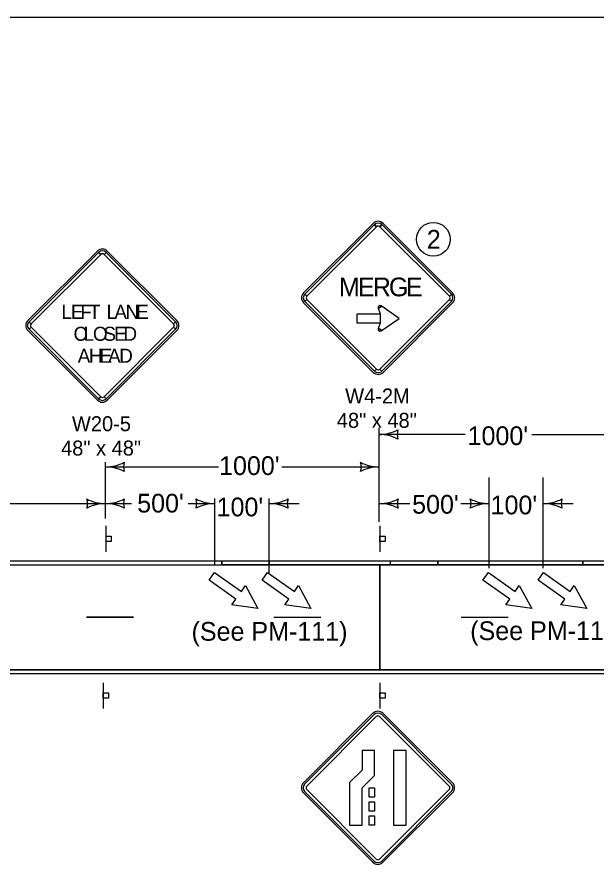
# Model space of a CAD drawing. Extents: x -2135039 to 114557, y -2139150 to -409929.
# Drawn here: x -2134068 to -2133449, y -2137945 to -2137036 of the extents above; entities that cross this region are included whole.
import ezdxf

# ---------------------------------------------------------------- set-up
doc = ezdxf.new("R2010")
doc.units = 0
for name, color, linetype in [('dsnStdLabel', 7, 'Continuous'), ('dsnStdLineWork', 7, 'Continuous'), ('dsnStdNote', 7, 'Continuous'), ('dsnStdShading', 7, 'Continuous'), ('Level 1', 7, 'Continuous'), ('StdDimension', 7, 'Continuous')]:
    doc.layers.add(name, color=color, linetype=linetype)

msp = doc.modelspace()

# ---------------------------------------------------------------- linework, layer by layer
at = {"layer": 'dsnStdLabel'}
for p, q in [((-2133688.07, -2137256.29), (-2133762.32, -2137330.54)), ((-2133686.75, -2137257.62), (-2133684.54, -2137259.83)), ((-2133681, -2137259.83), (-2133678.79, -2137257.62)), ((-2133603.22, -2137330.54), (-2133677.47, -2137256.29)), ((-2133982.39, -2137285.89), (-2134056.63, -2137360.14)), ((-2133897.53, -2137360.14), (-2133971.78, -2137285.89)), ((-2133981.06, -2137287.22), (-2133978.85, -2137289.43)), ((-2133975.32, -2137289.43), (-2133973.11, -2137287.22)), ((-2133758.79, -2137334.08), (-2133760.99, -2137331.87)), ((-2133760.99, -2137339.82), (-2133758.79, -2137337.61)), ((-2133604.55, -2137331.87), (-2133606.76, -2137334.08)), ((-2133606.76, -2137337.61), (-2133604.55, -2137339.82)), ((-2133762.32, -2137341.15), (-2133688.07, -2137415.39)), ((-2133682.67, -2137346.8), (-2133680.74, -2137346.16)), ((-2133680.74, -2137346.16), (-2133679.65, -2137344.44)), ((-2133677.47, -2137415.39), (-2133603.22, -2137341.15)), ((-2134053.1, -2137363.68), (-2134055.31, -2137361.47)), ((-2134055.31, -2137369.42), (-2134053.1, -2137367.21)), ((-2133898.86, -2137361.47), (-2133901.07, -2137363.68)), ((-2133901.07, -2137367.21), (-2133898.86, -2137369.42)), ((-2134056.63, -2137370.75), (-2133982.39, -2137444.99)), ((-2133971.78, -2137444.99), (-2133897.53, -2137370.75)), ((-2133680.74, -2137369.28), (-2133682.67, -2137368.63)), ((-2133679.65, -2137371), (-2133680.74, -2137369.28)), ((-2133684.54, -2137411.86), (-2133686.75, -2137414.07)), ((-2133678.79, -2137414.07), (-2133681, -2137411.86)), ((-2133978.85, -2137441.46), (-2133981.06, -2137443.67)), ((-2133973.11, -2137443.67), (-2133975.32, -2137441.46)), ((-2133973.24, -2137579.41), (-2133973.24, -2137606.91)), ((-2133680.95, -2137579.41), (-2133680.95, -2137606.91)), ((-2133976.34, -2137746.91), (-2133976.34, -2137774.41)), ((-2133680.95, -2137746.91), (-2133680.95, -2137774.41)), ((-2133688.27, -2137779.43), (-2133762.52, -2137853.68)), ((-2133762.52, -2137853.68), (-2133688.27, -2137779.44)), ((-2133761.19, -2137855.01), (-2133686.95, -2137780.76)), ((-2133684.74, -2137782.97), (-2133758.98, -2137857.22)), ((-2133688.27, -2137779.44), (-2133688.27, -2137779.43)), ((-2133684.74, -2137782.97), (-2133684.74, -2137782.97)), ((-2133606.95, -2137857.22), (-2133681.2, -2137782.97)), ((-2133678.99, -2137780.76), (-2133604.74, -2137855.01)), ((-2133603.42, -2137853.68), (-2133677.67, -2137779.43)), ((-2133677.67, -2137779.44), (-2133603.42, -2137853.68)), ((-2133688.27, -2137938.54), (-2133762.52, -2137864.29)), ((-2133762.52, -2137864.29), (-2133688.27, -2137938.54)), ((-2133686.95, -2137937.21), (-2133761.19, -2137862.96)), ((-2133758.98, -2137860.75), (-2133684.74, -2137935)), ((-2133681.2, -2137935), (-2133606.95, -2137860.75)), ((-2133604.74, -2137862.96), (-2133678.99, -2137937.21)), ((-2133603.42, -2137864.29), (-2133677.67, -2137938.54)), ((-2133677.67, -2137938.54), (-2133603.42, -2137864.29))]:
    msp.add_line(p, q, dxfattribs=at)
for points in [[(-2133686.75, -2137257.62), (-2133760.99, -2137331.87), (-2133758.79, -2137334.08), (-2133684.54, -2137259.83), (-2133686.75, -2137257.62)], [(-2133604.55, -2137331.87), (-2133678.79, -2137257.62), (-2133681, -2137259.83), (-2133606.76, -2137334.08), (-2133604.55, -2137331.87)], [(-2133981.06, -2137287.22), (-2134055.31, -2137361.47), (-2134053.1, -2137363.68), (-2133978.85, -2137289.43), (-2133981.06, -2137287.22)], [(-2133898.86, -2137361.47), (-2133973.11, -2137287.22), (-2133975.32, -2137289.43), (-2133901.07, -2137363.68), (-2133898.86, -2137361.47)], [(-2133760.99, -2137339.82), (-2133686.75, -2137414.07), (-2133684.54, -2137411.86), (-2133758.79, -2137337.61), (-2133760.99, -2137339.82)], [(-2133678.79, -2137414.07), (-2133604.55, -2137339.82), (-2133606.76, -2137337.61), (-2133681, -2137411.86), (-2133678.79, -2137414.07)], [(-2133660.43, -2137357.72), (-2133679.65, -2137344.44), (-2133680.74, -2137346.16), (-2133682.67, -2137346.8), (-2133680.68, -2137352.72), (-2133680.68, -2137362.72), (-2133682.67, -2137368.63), (-2133680.74, -2137369.28), (-2133679.65, -2137371), (-2133660.43, -2137357.72)], [(-2133705.11, -2137362.72), (-2133705.11, -2137352.72), (-2133680.68, -2137352.72), (-2133680.68, -2137362.72), (-2133705.11, -2137362.72)], [(-2134055.31, -2137369.42), (-2133981.06, -2137443.67), (-2133978.85, -2137441.46), (-2134053.1, -2137367.21), (-2134055.31, -2137369.42)], [(-2133973.11, -2137443.67), (-2133898.86, -2137369.42), (-2133901.07, -2137367.21), (-2133975.32, -2137441.46), (-2133973.11, -2137443.67)], [(-2133973.14, -2137595.86), (-2133973.14, -2137590.23), (-2133967.52, -2137590.23), (-2133967.52, -2137595.86)], [(-2133680.86, -2137595.86), (-2133680.86, -2137590.23), (-2133675.23, -2137590.23), (-2133675.23, -2137595.86)], [(-2133976.24, -2137763.35), (-2133976.24, -2137757.73), (-2133970.62, -2137757.73), (-2133970.62, -2137763.35)], [(-2133680.86, -2137763.35), (-2133680.86, -2137757.73), (-2133675.23, -2137757.73), (-2133675.23, -2137763.35)], [(-2133699.97, -2137840.14), (-2133713.22, -2137853.39), (-2133713.22, -2137898.99), (-2133699.72, -2137898.99), (-2133699.72, -2137858.99), (-2133686.47, -2137845.73), (-2133686.47, -2137818.99), (-2133699.97, -2137818.99)], [(-2133666.22, -2137818.99), (-2133666.22, -2137898.99), (-2133652.72, -2137898.99), (-2133652.72, -2137818.99)], [(-2133692.47, -2137858.99), (-2133686.47, -2137858.99), (-2133686.47, -2137868.99), (-2133692.47, -2137868.99)], [(-2133692.47, -2137873.99), (-2133686.47, -2137873.99), (-2133686.47, -2137883.99), (-2133692.47, -2137883.99)], [(-2133692.47, -2137888.99), (-2133686.47, -2137888.99), (-2133686.47, -2137898.99), (-2133692.47, -2137898.99)]]:
    msp.add_lwpolyline(points, close=True, dxfattribs=at)
for points in [[(-2133686.95, -2137780.76), (-2133761.19, -2137855.01)], [(-2133684.74, -2137782.97), (-2133758.99, -2137857.22)], [(-2133606.95, -2137857.22), (-2133681.2, -2137782.97)], [(-2133604.74, -2137855.01), (-2133678.99, -2137780.76)], [(-2133761.19, -2137862.96), (-2133686.95, -2137937.21)], [(-2133758.99, -2137860.75), (-2133684.74, -2137935)], [(-2133681.2, -2137935), (-2133606.95, -2137860.75)], [(-2133678.99, -2137937.21), (-2133604.74, -2137862.96)]]:
    msp.add_lwpolyline(points, dxfattribs=at)
for centre, radius, start, end in [((-2133682.77, -2137261.6), 7.5, 44.99999, 134.99974), ((-2133682.77, -2137261.6), 5.62, 44.99999, 134.99974), ((-2133682.77, -2137261.6), 2.5, 44.99999, 134.99974), ((-2133977.08, -2137291.2), 7.5, 44.99999, 134.99974), ((-2133977.08, -2137291.2), 5.62, 44.99999, 134.99974), ((-2133977.08, -2137291.2), 2.5, 44.99999, 134.99974), ((-2133757.02, -2137335.84), 7.5, 134.99974, 224.99995), ((-2133608.53, -2137335.84), 7.5, 315.00016, 44.9998), ((-2133757.02, -2137335.84), 5.62, 134.99974, 224.99995), ((-2133757.02, -2137335.84), 2.5, 134.99974, 224.99995), ((-2133608.53, -2137335.84), 2.5, 315.00016, 44.9998), ((-2133608.53, -2137335.84), 5.62, 315.00016, 44.9998), ((-2133680.74, -2137346.16), 2.03, 57.68768, 198.58144), ((-2134051.33, -2137365.44), 7.5, 134.99974, 224.99995), ((-2134051.33, -2137365.44), 5.62, 134.99974, 224.99995), ((-2134051.33, -2137365.44), 2.5, 134.99974, 224.99995), ((-2133902.84, -2137365.44), 2.5, 315.00016, 44.9998), ((-2133902.84, -2137365.44), 5.62, 315.00016, 44.9998), ((-2133902.84, -2137365.44), 7.5, 315.00016, 44.9998), ((-2133680.74, -2137369.28), 2.03, 161.41825, 302.31259), ((-2133682.77, -2137410.09), 2.5, 224.99995, 315.00016), ((-2133682.77, -2137410.09), 7.5, 224.99995, 315.00016), ((-2133682.77, -2137410.09), 5.62, 224.99995, 315.00016), ((-2133977.08, -2137439.69), 7.5, 224.99995, 315.00016), ((-2133977.08, -2137439.69), 5.62, 224.99995, 315.00016), ((-2133977.08, -2137439.69), 2.5, 224.99995, 315.00016), ((-2133682.97, -2137784.74), 7.5, 45.00026, 135.00001), ((-2133682.97, -2137784.74), 7.5, 45.00026, 135.00001), ((-2133682.97, -2137784.74), 5.63, 45.00026, 135.00001), ((-2133682.97, -2137784.74), 5.63, 45.00026, 135.00001), ((-2133682.97, -2137784.74), 2.5, 45.00026, 135.00001), ((-2133682.97, -2137784.74), 2.5, 45.00026, 135.00001), ((-2133757.22, -2137858.99), 7.5, 135.0002, 224.99984), ((-2133757.22, -2137858.99), 7.5, 135.0002, 224.99984), ((-2133757.22, -2137858.99), 5.63, 135.0002, 224.99984), ((-2133757.22, -2137858.99), 5.63, 135.0002, 224.99984), ((-2133757.22, -2137858.99), 2.5, 135.0002, 224.99984), ((-2133757.22, -2137858.99), 2.5, 135.0002, 224.99984), ((-2133608.72, -2137858.99), 2.5, 315.00005, 45.00026), ((-2133608.72, -2137858.99), 2.5, 315.00005, 45.00026), ((-2133608.72, -2137858.99), 5.63, 315.00005, 45.00026), ((-2133608.72, -2137858.99), 5.63, 315.00005, 45.00026), ((-2133608.72, -2137858.99), 7.5, 315.00005, 45.00026), ((-2133608.72, -2137858.99), 7.5, 315.00005, 45.00026), ((-2133682.97, -2137933.23), 7.5, 224.99984, 315.00005), ((-2133682.97, -2137933.23), 7.5, 224.99984, 315.00005), ((-2133682.97, -2137933.23), 5.63, 224.99984, 315.00005), ((-2133682.97, -2137933.23), 5.63, 224.99984, 315.00005), ((-2133682.97, -2137933.23), 2.5, 224.99984, 315.00005), ((-2133682.97, -2137933.23), 2.5, 224.99984, 315.00005)]:
    msp.add_arc(centre, radius, start, end, dxfattribs=at)
at = {"layer": 'dsnStdLineWork'}
for p, q in [((-2134890.21, -2137620.91), (-2133281.94, -2137620.91)), ((-2133863.14, -2137637.37), (-2133857.4, -2137629.18)), ((-2133857.4, -2137629.18), (-2133828.74, -2137649.25)), ((-2133806.58, -2137637.37), (-2133800.85, -2137629.18)), ((-2133800.85, -2137629.18), (-2133772.18, -2137649.25)), ((-2133570.85, -2137637.37), (-2133565.11, -2137629.18)), ((-2133565.11, -2137629.18), (-2133536.45, -2137649.25)), ((-2133512.08, -2137637.37), (-2133506.34, -2137629.18)), ((-2133506.34, -2137629.18), (-2133477.68, -2137649.25)), ((-2133834.47, -2137657.44), (-2133863.14, -2137637.37)), ((-2133777.92, -2137657.44), (-2133806.58, -2137637.37)), ((-2133542.19, -2137657.44), (-2133570.85, -2137637.37)), ((-2133483.42, -2137657.44), (-2133512.08, -2137637.37)), ((-2133828.74, -2137649.25), (-2133824.44, -2137643.11)), ((-2133824.44, -2137643.11), (-2133811.13, -2137667.68)), ((-2133772.18, -2137649.25), (-2133767.88, -2137643.11)), ((-2133767.88, -2137643.11), (-2133754.57, -2137667.68)), ((-2133536.45, -2137649.25), (-2133532.15, -2137643.11)), ((-2133532.15, -2137643.11), (-2133518.84, -2137667.68)), ((-2133477.68, -2137649.25), (-2133473.38, -2137643.11)), ((-2133473.38, -2137643.11), (-2133460.07, -2137667.68)), ((-2133838.78, -2137663.58), (-2133834.47, -2137657.44)), ((-2133782.22, -2137663.58), (-2133777.92, -2137657.44)), ((-2133546.49, -2137663.58), (-2133542.19, -2137657.44)), ((-2133487.72, -2137663.58), (-2133483.42, -2137657.44)), ((-2133811.13, -2137667.68), (-2133838.78, -2137663.58)), ((-2133754.57, -2137667.68), (-2133782.22, -2137663.58)), ((-2133518.84, -2137667.68), (-2133546.49, -2137663.58)), ((-2133460.07, -2137667.68), (-2133487.72, -2137663.58)), ((-2134898.17, -2137732.92), (-2132869.81, -2137732.92))]:
    msp.add_line(p, q, dxfattribs=at)
for points in [[(-2133993.94, -2137676.51), (-2133943.95, -2137676.51)], [(-2133993.94, -2137676.9), (-2133943.95, -2137676.9)], [(-2133793.97, -2137676.9), (-2133743.98, -2137676.9)], [(-2133793.97, -2137676.9), (-2133743.98, -2137676.9)], [(-2133594, -2137676.9), (-2133544.01, -2137676.9)]]:
    msp.add_lwpolyline(points, dxfattribs=at)
at = {"layer": 'dsnStdNote'}
msp.add_circle((-2133623.81, -2137273.27), 18, dxfattribs=at)
at = {"layer": 'dsnStdShading'}
for p, q in [((-2133849.72, -2137616.91), (-2134894.19, -2137616.91)), ((-2133857.09, -2137616.91), (-2134894.19, -2137616.91)), ((-2134890.2, -2137620.91), (-2133857.09, -2137620.91)), ((-2133857.09, -2137620.91), (-2133857.09, -2137616.91)), ((-2133849.72, -2137620.91), (-2133849.72, -2137616.91)), ((-2133798.9, -2137616.91), (-2133849.72, -2137616.91)), ((-2133849.72, -2137616.91), (-2133849.72, -2137620.91)), ((-2133849.72, -2137620.91), (-2133798.9, -2137620.91)), ((-2133564.44, -2137616.91), (-2133798.9, -2137616.91)), ((-2133798.9, -2137616.91), (-2133798.9, -2137620.91)), ((-2133798.9, -2137620.91), (-2133798.9, -2137616.91)), ((-2133798.9, -2137620.91), (-2133564.44, -2137620.91)), ((-2133680.95, -2137732.91), (-2133680.95, -2137620.91)), ((-2133619.09, -2137620.91), (-2133680.95, -2137620.91)), ((-2133680.95, -2137620.91), (-2133680.95, -2137732.91)), ((-2133619.09, -2137616.91), (-2133669.91, -2137616.91)), ((-2133669.91, -2137616.91), (-2133669.91, -2137620.91)), ((-2133669.91, -2137620.91), (-2133619.09, -2137620.91)), ((-2133464.46, -2137616.91), (-2133619.09, -2137616.91)), ((-2133619.09, -2137616.91), (-2133619.09, -2137620.91)), ((-2133619.09, -2137620.91), (-2133619.09, -2137616.91)), ((-2133464.46, -2137616.91), (-2133619.09, -2137616.91)), ((-2133619.09, -2137616.91), (-2133619.09, -2137620.91)), ((-2133619.09, -2137620.91), (-2133464.46, -2137620.91)), ((-2133619.09, -2137620.91), (-2133464.46, -2137620.91)), ((-2133464.46, -2137620.91), (-2133619.09, -2137620.91)), ((-2133564.44, -2137620.91), (-2133564.44, -2137616.91)), ((-2133464.46, -2137620.91), (-2133464.46, -2137616.91)), ((-2133464.46, -2137620.91), (-2133464.46, -2137616.91)), ((-2132633.8, -2137616.91), (-2133464.46, -2137616.91)), ((-2133464.46, -2137616.91), (-2133464.46, -2137620.91)), ((-2133223.54, -2137620.91), (-2133464.46, -2137620.91)), ((-2133464.46, -2137620.91), (-2133223.54, -2137620.91)), ((-2133102.63, -2137732.91), (-2134898.19, -2137732.91)), ((-2134898.19, -2137732.91), (-2133680.95, -2137732.91)), ((-2134894.19, -2137736.9), (-2133075.86, -2137736.9)), ((-2134894.19, -2137736.91), (-2133104.35, -2137736.9)), ((-2133680.95, -2137732.91), (-2133102.63, -2137732.91))]:
    msp.add_line(p, q, dxfattribs=at)
msp.add_lwpolyline([(-2133680.95, -2137620.91), (-2133798.9, -2137620.91), (-2133849.72, -2137620.91)], dxfattribs=at)
at = {"layer": 'Level 1'}
msp.add_lwpolyline([(-2134934.44, -2137035.95), (-2131799.45, -2137035.95), (-2131799.45, -2139045.94), (-2134934.44, -2139045.94)], close=True, dxfattribs=at)
at = {"layer": 'StdDimension'}
for p, q in [((-2133681.62, -2137575.14), (-2133681.62, -2137474.5)), ((-2133590.02, -2137481.63), (-2133681.62, -2137481.63)), ((-2133518.81, -2137481.63), (-2133415.82, -2137481.63)), ((-2133973.69, -2137571.41), (-2133973.69, -2137511.37)), ((-2133973.89, -2137516.37), (-2133853.15, -2137516.37)), ((-2133785.59, -2137516.37), (-2133681.62, -2137516.37)), ((-2133564.44, -2137624.53), (-2133564.44, -2137527.63)), ((-2133506.61, -2137624.53), (-2133506.61, -2137527.63)), ((-2134090.29, -2137555.52), (-2133973.89, -2137555.52)), ((-2133973.09, -2137555.52), (-2133946, -2137555.52)), ((-2133885.68, -2137555.52), (-2133857.09, -2137555.52)), ((-2133857.09, -2137621.18), (-2133857.09, -2137549.93)), ((-2133798.9, -2137629.37), (-2133798.9, -2137549.93)), ((-2133798.9, -2137555.52), (-2133766.9, -2137555.52)), ((-2133680.8, -2137555.52), (-2133648.94, -2137555.52)), ((-2133594.48, -2137555.52), (-2133564.44, -2137555.52)), ((-2133506.61, -2137555.52), (-2133474.61, -2137555.52))]:
    msp.add_line(p, q, dxfattribs=at)
for centre, radius, start, end in [((-2133681.62, -2137439.13), 42.5, 270, 298.07249), ((-2133645.98, -2137481.63), 16.42, 162.26665, 197.73335), ((-2133681.62, -2137524.13), 42.5, 61.92751, 90), ((-2133973.69, -2137473.87), 42.5, 270, 298.07249), ((-2133938.05, -2137516.37), 16.42, 162.26665, 197.73335), ((-2133717.25, -2137516.37), 16.42, 342.26665, 17.73335), ((-2133681.62, -2137473.87), 42.5, 241.92751, 270), ((-2133973.69, -2137558.87), 42.5, 61.92751, 90), ((-2133681.62, -2137558.87), 42.5, 90, 118.07249), ((-2134009.33, -2137555.52), 16.42, 342.26665, 17.73335), ((-2133973.69, -2137513.02), 42.5, 241.92751, 270), ((-2133973.69, -2137598.01), 42.5, 90, 118.07249), ((-2133973.69, -2137513.02), 42.5, 270, 298.07249), ((-2133973.69, -2137598.01), 42.5, 61.92751, 90), ((-2133938.05, -2137555.52), 16.42, 162.26665, 197.73335), ((-2133892.73, -2137555.52), 16.42, 342.26665, 17.73335), ((-2133857.09, -2137513.02), 42.5, 241.92751, 270), ((-2133857.09, -2137598.01), 42.5, 90, 118.07249), ((-2133798.9, -2137513.02), 42.5, 270, 298.07249), ((-2133798.9, -2137598.01), 42.5, 61.92751, 90), ((-2133763.26, -2137555.52), 16.42, 162.26665, 197.73335), ((-2133681.4, -2137513.02), 42.5, 270, 298.07249), ((-2133681.4, -2137598.01), 42.5, 61.92751, 90), ((-2133645.76, -2137555.52), 16.42, 162.26665, 197.73335), ((-2133600.07, -2137555.52), 16.42, 342.26665, 17.73335), ((-2133564.44, -2137513.02), 42.5, 241.92751, 270), ((-2133564.44, -2137598.01), 42.5, 90, 118.07249), ((-2133506.61, -2137513.02), 42.5, 270, 298.07249), ((-2133506.61, -2137598.01), 42.5, 61.92751, 90), ((-2133470.97, -2137555.52), 16.42, 162.26665, 197.73335)]:
    msp.add_arc(centre, radius, start, end, dxfattribs=at)

# ---------------------------------------------------------------- texts
at = {"layer": 'dsnStdLabel'}
for s, height, p in [('M', 20, (-2133724.65, -2137334.13)), ('E', 20, (-2133704.45, -2137334.13)), ('R', 20, (-2133688.47, -2137334.13)), ('G', 20, (-2133671.25, -2137334.13)), ('E', 20, (-2133653.08, -2137334.13)), ('L', 15, (-2134020.69, -2137358.26)), ('E', 15, (-2134010.66, -2137358.26)), ('F', 15, (-2134000.62, -2137358.26)), ('T', 15, (-2133991.42, -2137358.26)), ('L', 15, (-2133972.6, -2137358.26)), ('A', 15, (-2133964.25, -2137358.26)), ('N', 15, (-2133952.34, -2137358.26)), ('E', 15, (-2133940.98, -2137358.26)), ('C', 15, (-2134007.87, -2137381.69)), ('L', 15, (-2133997.13, -2137381.69)), ('O', 15, (-2133987.1, -2137381.69)), ('S', 15, (-2133975.9, -2137381.69)), ('E', 15, (-2133964.53, -2137381.69)), ('D', 15, (-2133954.5, -2137381.69)), ('A', 15, (-2134003.32, -2137405.13)), ('H', 15, (-2133991.44, -2137405.13)), ('E', 15, (-2133980.11, -2137405.13)), ('A', 15, (-2133970.93, -2137405.13)), ('D', 15, (-2133959.05, -2137405.13)), ('W4-2M', 16, (-2133717.94, -2137448.59)), ('48" x 48"', 16, (-2133726.84, -2137474.59)), ('W20-5', 16, (-2134009.55, -2137478.19)), ('48" x 48"', 16, (-2134021.15, -2137504.19)), ('(See PM-111)', 20, (-2133881.9, -2137701.94)), ('(See PM-111)', 20, (-2133584.5, -2137701.21))]:
    msp.add_text(s, height=height, dxfattribs=at).set_placement(p)
at = {"layer": 'dsnStdNote'}
msp.add_text('2', height=20, dxfattribs=at).set_placement((-2133630.83, -2137283.27))
at = {"layer": 'StdDimension'}
for s, p in [("1000'", (-2133587.3, -2137493.02)), ("1000'", (-2133852.54, -2137524.99)), ("500'", (-2133939.91, -2137565.05)), ("100'", (-2133855.17, -2137569.13)), ("500'", (-2133646.48, -2137566.24)), ("100'", (-2133562.76, -2137566.98))]:
    msp.add_text(s, height=20, dxfattribs=at).set_placement(p)

doc.saveas('drawing.dxf')
